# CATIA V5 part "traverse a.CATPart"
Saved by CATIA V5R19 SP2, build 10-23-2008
Part number: traverse a
Property "diametre trou traverse a": 2 mm
Publications: "diametre arbre entree", "Esquisse.1"
Bounding box of the stored display mesh (mm): x -60 to -55, y -13.8 to 13.8, z -5 to 5
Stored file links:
  C:\Users\Thinkmotion2\Desktop\Pack 1\IAO_2010_1396_fvigouroux\vigouroux\vigouroux\traverse a.CATPart
  C:\Users\Thinkmotion2\Desktop\Pack 1\IAO_2010_1396_fvigouroux\vigouroux\vigouroux\mecanisme IAO.CATProduct
  C:\Users\Thinkmotion2\Desktop\Pack 1\IAO_2010_1396_fvigouroux\vigouroux\vigouroux\coulisseau.CATPart
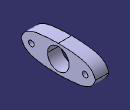
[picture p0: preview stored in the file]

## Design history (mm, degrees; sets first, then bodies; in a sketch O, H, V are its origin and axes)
External parameters (linked from other documents)
  `External.diametre arbre entree` = 4 mm
Set1
  Plane1: linked copy from another document
  Point1: linked copy from another document
  Plane2: linked copy from another document
Body1 (main body)
  Sketch1 on Plane1, origin (-55, 0, 0), H (0, 1, 0), V (0, 0, 1)
    circle A1 centre (0, 0) radius 4
    point P1 (0, 0)
    reference projected point E1 (0, 0) from Point1
    spline S1 through (-13.8, 0) (-12.8544, 1.9403) (-6.5593, 4.58) (0, 5)
    spline S2 through (13.8, 0) (12.8544, 1.9403) (6.5593, 4.58) (0, 5)
    spline S3 through (-13.8, 0) (-12.8544, -1.9403) (-6.5593, -4.58) (0, -5)
    spline S4 through (13.8, 0) (12.8544, -1.9403) (6.5593, -4.58) (0, -5)
    reference projected point E2 (0, 0) from Point1
    reference projected point E3 (0, 0) from Point1
    reference projected point E4 (0, 0) from Point1
    reference projected point E5 (0, 0) from Point1
    point P2 (-13.8, 0)
    point P3 (0, 5)
    point P4 (-6.5593, 4.58)
    point P5 (-12.8544, 1.9403)
    point P6 (0, 5)
    point P7 (13.8, 0)
    point P8 (6.5593, 4.58)
    point P9 (12.8544, 1.9403)
    point P10 (0, -5)
    point P11 (-13.8, 0)
    point P12 (-6.5593, -4.58)
    point P13 (-12.8544, -1.9403)
    point P14 (0, -5)
    point P15 (13.8, 0)
    point P16 (6.5593, -4.58)
    point P17 (12.8544, -1.9403)
    radius A1 = 4 {= `External.diametre arbre entree`}
    distance E1 P1 = 0
    distance E2 P6 = 5
    distance E3 P11 = 13.8
    distance E4 P4 = 8
    distance E5 P5 = 13
    coincidence: P2 H, P3 V, P2 P11, P3 P6, P7 P15, P10 P14
    symmetry: S1 S2 V, P3 P6 V, P2 P7 V, P4 P8 V, P5 P9 V, S1 S3 H, P3 P10 H, P2 P11 H, P4 P12 H, P5 P13 H, S3 S4 V, P10 P14 V, P11 P15 V, P12 P16 V, P13 P17 V
  Pad1: profile Sketch1, direction (-1, 0, 0), up to Plane2
  Sketch2 on start face of Pad1, origin (-55, 10.4133, 0), H (0, 1, 0), V (0, 0, 1)
    point P1 (-0.4133, 0)
    reference projected point E1 (-10.4133, 0) from Point1
    distance E1 P1 = 10
  Hole1: placed by Sketch2, at (-55, 10, 0) direction (-1, 0, 0), diameter 2, through (limit type 6)
  Mirror1: of Hole1, about zx-plane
